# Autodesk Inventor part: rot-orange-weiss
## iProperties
Created: 2004-10
Part Number: rot-orange-weiss
Document SubType Name: Modeling
Designer: sahrens
Manufacturer: Standard
Standards Organization: Custom
Author: sahrens
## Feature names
1. Extrusion1
2. Rundung2 [Fillet]
